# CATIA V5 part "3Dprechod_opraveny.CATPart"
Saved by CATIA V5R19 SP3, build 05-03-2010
Part number: Tp6016860__0-0.SLDPRT
Bounding box of the stored display mesh (mm): x -200.407 to 167.516, y -155.068 to 63.494, z 0 to 966.071
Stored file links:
  D:\Catia fórum\Modely - Otazky\3Dprechod_opraveny.CATPart
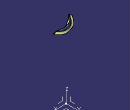
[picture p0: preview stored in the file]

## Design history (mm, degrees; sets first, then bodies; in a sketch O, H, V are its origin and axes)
AxisSystem1: origin (0, 0, 0), X (1, 0, 0), Y (0, 1, 0), Z (0, 0, 1)
Set1
  DatumCurve1 to DatumCurve272
  DatumSurface1 to DatumSurface4
  DatumCurve273 to DatumCurve284
  Join1: Elements (DatumSurface2; DatumSurface1; DatumSurface3; DatumSurface4)
Set2
  Loft1: Sections (DatumCurve24; DatumCurve23; DatumCurve22; DatumCurve21; DatumCurve20; DatumCurve19; DatumCurve18; DatumCurve17; DatumCurve16; DatumCurve15; DatumCurve14; DatumCurve13; DatumCurve12; DatumCurve11; DatumCurve10; DatumCurve9; DatumCurve8; DatumCurve7; DatumCurve6; DatumCurve5; DatumCurve4; DatumCurve3; DatumCurve2; DatumCurve1; DatumCurve28; DatumCurve27; DatumCurve26; DatumCurve25; DatumCurve29; DatumCurve30; DatumCurve31; DatumCurve32; DatumCurve33; DatumCurve34; DatumCurve35; DatumCurve36; DatumCurve37; DatumCurve38; DatumCurve39; DatumCurve40; DatumCurve41; DatumCurve42; DatumCurve43; DatumCurve44; DatumCurve45; DatumCurve46; DatumCurve47; DatumCurve48; DatumCurve49; DatumCurve50; DatumCurve51; DatumCurve52; DatumCurve53; DatumCurve54; DatumCurve55; DatumCurve57; DatumCurve58; DatumCurve56; DatumCurve59; DatumCurve60; DatumCurve61)
  Curve1: Elements (vertex of DatumCurve66; vertex of DatumCurve77; vertex of DatumCurve78; vertex of DatumCurve79; vertex of DatumCurve80; vertex of DatumCurve81; vertex of DatumCurve82; vertex of DatumCurve83; vertex of DatumCurve84; vertex of DatumCurve85; vertex of DatumCurve86; vertex of DatumCurve87)
  Curve2: Elements (vertex of DatumCurve66; vertex of DatumCurve77; vertex of DatumCurve78; vertex of DatumCurve79; vertex of DatumCurve80; vertex of DatumCurve81; vertex of DatumCurve82; vertex of DatumCurve83; vertex of DatumCurve84; vertex of DatumCurve85; vertex of DatumCurve86; vertex of DatumCurve87)
  Loft2: Sections (DatumCurve66; DatumCurve77; DatumCurve78; DatumCurve79; DatumCurve80; DatumCurve81; DatumCurve82; DatumCurve83; DatumCurve84; DatumCurve85; DatumCurve86; DatumCurve87), Guides (Curve1; Curve2)
  Loft3: Sections (DatumCurve87; DatumCurve88; DatumCurve89; DatumCurve90; DatumCurve91; DatumCurve92; DatumCurve94; DatumCurve96; DatumCurve97; DatumCurve99; DatumCurve101; DatumCurve103; DatumCurve105; DatumCurve107; DatumCurve109; DatumCurve110; DatumCurve113; DatumCurve122; DatumCurve119; DatumCurve116; DatumCurve127; DatumCurve124; DatumCurve135; DatumCurve132; DatumCurve139; DatumCurve143; DatumCurve146; DatumCurve150; DatumCurve155; DatumCurve160; DatumCurve165; DatumCurve170; DatumCurve175; DatumCurve179; DatumCurve183; DatumCurve188; DatumCurve193; DatumCurve197; DatumCurve201; DatumCurve206; DatumCurve210; DatumCurve214; DatumCurve218; DatumCurve222; DatumCurve225; DatumCurve227; DatumCurve229; DatumCurve230; DatumCurve231; DatumCurve233; DatumCurve235)
  Curve3: Elements DatumCurve2
  Curve4: Elements DatumCurve5
  Loft4: Sections (DatumCurve235; DatumCurve245; DatumCurve24), Guides (Curve3; Curve4)
  Curve5: Elements (vertex of DatumCurve61; vertex of DatumCurve62; vertex of DatumCurve63; vertex of DatumCurve64; vertex of DatumCurve65; vertex of DatumCurve75; vertex of DatumCurve74; vertex of DatumCurve73; vertex of DatumCurve72; vertex of DatumCurve71; vertex of DatumCurve70; vertex of DatumCurve69; vertex of DatumCurve68; vertex of DatumCurve67; vertex of DatumCurve66)
  Curve6: Elements (vertex of DatumCurve61; vertex of DatumCurve62; vertex of DatumCurve63; vertex of DatumCurve64; vertex of DatumCurve65; vertex of DatumCurve75; vertex of DatumCurve74; vertex of DatumCurve73; vertex of DatumCurve72; vertex of DatumCurve71; vertex of DatumCurve70; vertex of DatumCurve69; vertex of DatumCurve68; vertex of DatumCurve67; vertex of DatumCurve66)
  Loft5: Sections (DatumCurve61; DatumCurve278; DatumCurve76; DatumCurve75; DatumCurve74; DatumCurve73; DatumCurve72; DatumCurve71; DatumCurve70; DatumCurve69; DatumCurve68; DatumCurve67; DatumCurve66), Guides (Curve5; Curve6)
  DatumCurve285
  Point1: type OnCurve, Support DatumCurve285, Length 13.972
Set3 "Prechod"
  Point2: type OnCurve, Support edge of Loft3, Length 472.008
  StIsoparamCurveFeature1 "CATStIsoparamCurveFeatureName": Direction {line type PtDir, RefPoint Point2, Direction (756.2278, -541.9844, 137.7597), LENGTH 0, LENGTH 10}, Position Point2, Support Loft3
  Split1: ToCut Loft3, Cutting StIsoparamCurveFeature1
  StIsoparamCurveFeature2 "CATStIsoparamCurveFeatureName": Direction {line type PtDir, RefPoint {point type OnSurface, Support Split1, Length 12.1839, Direction (0.7406, 0.0691, -0.6684)}, Direction (-128.8178, 1165.2649, 178.9681), LENGTH 0, LENGTH 10}, Position {point type OnSurface, Support Split1, Length 12.1839, Direction (0.7406, 0.0691, -0.6684)}, Support Split1
  StIsoparamCurveFeature3 "CATStIsoparamCurveFeatureName": Direction {line type PtDir, RefPoint {point type OnSurface, Support Split1, Length 14.3233, Direction (-0.7163, -0.1643, 0.6781)}, Direction (756.2278, -541.9844, 137.7597), LENGTH 0, LENGTH 10}, Position {point type OnSurface, Support Split1, Length 14.3233, Direction (-0.7163, -0.1643, 0.6781)}, Support Split1
  Point3: type OnCurve, Support edge of Loft1, Length 373.791
  StIsoparamCurveFeature4 "CATStIsoparamCurveFeatureName": Direction {line type PtDir, RefPoint Point3, Direction (-960.035, 159.5936, 139.0333), LENGTH 0, LENGTH 10}, Position Point3, Support Loft1
  Split2: ToCut Loft1, Cutting StIsoparamCurveFeature4
  StIsoparamCurveFeature5 "CATStIsoparamCurveFeatureName": Direction {line type PtDir, RefPoint {point type OnSurface, Support Split2, Length 9.6082, Direction (-0.1177, -0.452, -0.8842)}, Direction (-960.035, 159.5936, 139.0333), LENGTH 0, LENGTH 10}, Position {point type OnSurface, Support Split2, Length 9.6082, Direction (-0.1177, -0.452, -0.8842)}, Support Split2
  StIsoparamCurveFeature6 "CATStIsoparamCurveFeatureName": Direction {line type PtDir, RefPoint {point type OnSurface, Support Split2, Length 9.4905, Direction (0.0879, 0.4566, 0.8853)}, Direction (-960.035, 159.5936, 139.0333), LENGTH 0, LENGTH 10}, Position {point type OnSurface, Support Split2, Length 9.4905, Direction (0.0879, 0.4566, 0.8853)}, Support Split2
  Point4: type OnCurve, Support DatumCurve285, Length 2.139
  Point5: type OnCurve, Support DatumCurve285, Length 28.5
  Curve7: Elements Body1
  Curve8: Elements Body1
  Loft6: Sections (Curve8; Curve7), Guides ({loftguide GuideCurve edge of Loft3, GuideTangent Loft3}; DatumCurve285; {loftguide GuideCurve edge of Loft1, GuideTangent Loft1})
  Fill1: Boundary ({fillboundary BoundaryWire edge of Loft3, Support Loft3}; Curve4; {fillboundary BoundaryWire edge of Loft1, Support Loft1}; {fillboundary BoundaryWire Curve8, Support Loft6})
  Fill2: Boundary ({fillboundary BoundaryWire Curve7, Support Loft6}; {fillboundary BoundaryWire edge of Loft1, Support Loft1}; Curve3; DatumCurve285)
  Fill3: Boundary ({fillboundary BoundaryWire edge of Loft3, Support Loft3}; {fillboundary BoundaryWire Curve7, Support Loft6}; {fillboundary BoundaryWire DatumCurve285, Support Fill2}; Curve3)
  Join2: Elements (Loft6; Fill1; Fill2; Fill3)
Body1 (main body)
